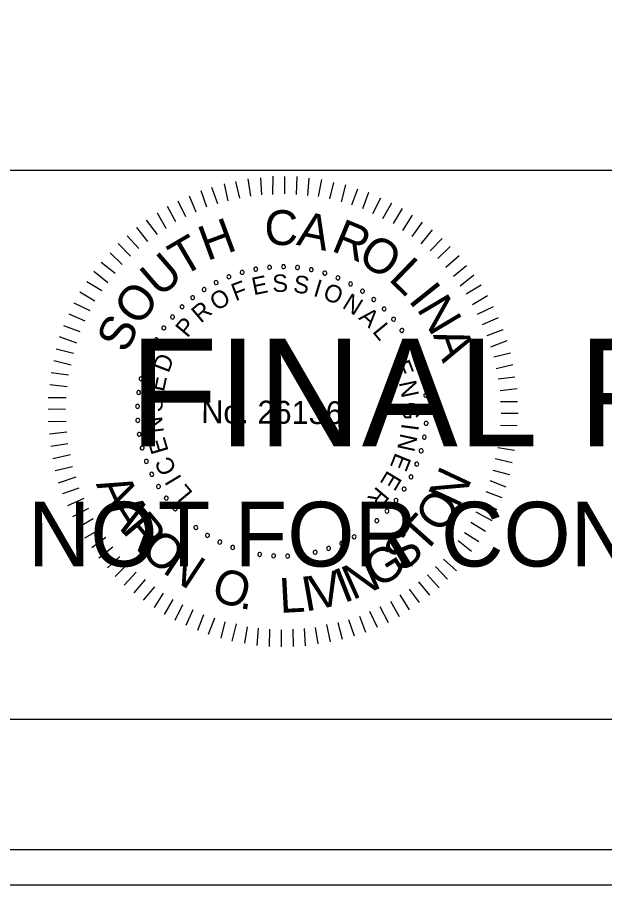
# Model space of a CAD drawing. Extents: x 967 to 1326, y 964 to 3704.
# Drawn here: x 1170.56 to 1189.3, y 1243.72 to 1271.36 of the extents above; entities that cross this region are included whole.
import ezdxf

# ---------------------------------------------------------------- set-up
doc = ezdxf.new("R2010")
doc.units = 0
for name, color, linetype in [('RD_SHT_Bndy', 7, 'Continuous'), ('RD_SHT_IplotShp', 7, 'Continuous'), ('RD_SHT_Misc1', 7, 'Continuous'), ('RD_SHT_Misc2', 7, 'Continuous'), ('RD_XS_TX_Station', 7, 'Continuous')]:
    doc.layers.add(name, color=color, linetype=linetype)

msp = doc.modelspace()

# ---------------------------------------------------------------- linework, layer by layer
at = {"layer": 'RD_SHT_Bndy'}
for p, q in [((996.114, 1266.486), (1323.886, 1266.486)), ((1323.886, 1248.983), (996.114, 1248.983))]:
    msp.add_line(p, q, dxfattribs=at)
at = {"layer": 'RD_SHT_IplotShp'}
for points in [[(967.409, 1243.72), (1326.285, 1243.72), (1326.285, 1463.72), (967.409, 1463.72)], [(988.525, 1244.84), (1326.285, 1244.84), (1326.285, 1462.6), (988.525, 1462.6)]]:
    msp.add_lwpolyline(points, close=True, dxfattribs=at)
at = {"layer": 'RD_SHT_Misc1'}
for p, q in [((1178.01, 1265.663), (1177.93, 1266.209)), ((1178.364, 1265.699), (1178.33, 1266.244)), ((1178.717, 1265.719), (1178.722, 1266.295)), ((1179.093, 1265.739), (1179.098, 1266.292)), ((1179.469, 1265.713), (1179.489, 1266.288)), ((1179.829, 1265.687), (1179.872, 1266.231)), ((1180.174, 1265.646), (1180.271, 1266.19)), ((1176.964, 1265.419), (1176.769, 1265.935)), ((1177.287, 1265.508), (1177.169, 1266.054)), ((1177.657, 1265.597), (1177.53, 1266.128)), ((1180.535, 1265.573), (1180.662, 1266.102)), ((1180.902, 1265.478), (1181.045, 1266.022)), ((1176.264, 1265.156), (1176.053, 1265.657)), ((1176.61, 1265.306), (1176.423, 1265.83)), ((1181.231, 1265.384), (1181.428, 1265.896)), ((1181.584, 1265.265), (1181.78, 1265.786)), ((1175.933, 1265.005), (1175.699, 1265.506)), ((1181.905, 1265.109), (1182.154, 1265.606)), ((1182.226, 1264.953), (1182.506, 1265.45)), ((1175.308, 1264.634), (1175.036, 1265.12)), ((1175.624, 1264.846), (1175.352, 1265.332)), ((1182.562, 1264.789), (1182.85, 1265.27)), ((1175.03, 1264.445), (1174.681, 1264.9)), ((1182.86, 1264.572), (1183.163, 1265.053)), ((1183.158, 1264.378), (1183.484, 1264.828)), ((1174.729, 1264.217), (1174.372, 1264.665)), ((1183.447, 1264.145), (1183.811, 1264.587)), ((1174.435, 1263.997), (1174.062, 1264.399)), ((1183.729, 1263.92), (1184.116, 1264.316)), ((1174.172, 1263.753), (1173.776, 1264.148)), ((1183.98, 1263.672), (1184.368, 1264.061)), ((1173.909, 1263.479), (1173.52, 1263.858)), ((1184.232, 1263.394), (1184.657, 1263.767)), ((1173.684, 1263.197), (1173.242, 1263.546)), ((1184.475, 1263.108), (1184.892, 1263.45)), ((1173.451, 1262.9), (1173.009, 1263.256)), ((1184.687, 1262.807), (1185.128, 1263.156)), ((1173.257, 1262.64), (1172.776, 1262.936)), ((1173.039, 1262.312), (1172.559, 1262.6)), ((1184.885, 1262.544), (1185.355, 1262.832)), ((1185.081, 1262.213), (1185.56, 1262.493)), ((1172.883, 1262.006), (1172.379, 1262.256)), ((1185.24, 1261.904), (1185.756, 1262.145)), ((1172.727, 1261.677), (1172.215, 1261.904)), ((1185.399, 1261.573), (1185.907, 1261.791)), ((1172.571, 1261.333), (1172.051, 1261.53)), ((1185.549, 1261.226), (1186.057, 1261.414)), ((1172.461, 1260.974), (1171.91, 1261.178)), ((1185.669, 1260.865), (1186.185, 1261.06)), ((1172.351, 1260.652), (1171.807, 1260.787)), ((1185.759, 1260.541), (1186.297, 1260.667)), ((1172.286, 1260.276), (1171.727, 1260.419)), ((1185.832, 1260.165), (1186.371, 1260.298)), ((1172.191, 1259.955), (1171.647, 1260.029)), ((1185.906, 1259.842), (1186.436, 1259.906)), ((1172.15, 1259.587), (1171.598, 1259.653)), ((1185.964, 1259.473), (1186.51, 1259.53)), ((1172.124, 1259.234), (1171.548, 1259.239)), ((1185.977, 1259.12), (1186.514, 1259.115)), ((1172.105, 1258.866), (1171.545, 1258.871)), ((1185.997, 1258.751), (1186.542, 1258.747)), ((1172.118, 1258.482), (1171.542, 1258.471)), ((1185.971, 1258.368), (1186.508, 1258.348)), ((1172.138, 1258.136), (1171.585, 1258.072)), ((1185.952, 1258.022), (1186.497, 1257.949)), ((1172.173, 1257.768), (1171.627, 1257.688)), ((1185.888, 1257.655), (1186.417, 1257.566)), ((1172.262, 1257.414), (1171.701, 1257.296)), ((1185.808, 1257.302), (1186.345, 1257.175)), ((1172.321, 1257.037), (1171.774, 1256.911)), ((1185.729, 1256.926), (1186.265, 1256.792)), ((1172.425, 1256.707), (1171.871, 1256.519)), ((1185.634, 1256.597), (1186.146, 1256.401)), ((1172.53, 1256.36), (1172.007, 1256.173)), ((1185.508, 1256.253), (1186.013, 1256.057)), ((1172.681, 1256.029), (1172.165, 1255.788)), ((1172.831, 1255.705), (1172.323, 1255.441)), ((1185.352, 1255.924), (1185.857, 1255.675)), ((1185.188, 1255.603), (1185.7, 1255.33)), ((1172.982, 1255.374), (1172.497, 1255.094)), ((1185.024, 1255.274), (1185.498, 1254.987)), ((1173.194, 1255.042), (1172.709, 1254.762)), ((1184.822, 1254.946), (1185.288, 1254.658)), ((1173.384, 1254.78), (1172.936, 1254.453)), ((1184.62, 1254.687), (1185.055, 1254.353)), ((1173.612, 1254.478), (1173.164, 1254.129)), ((1184.403, 1254.389), (1184.814, 1254.033)), ((1173.832, 1254.177), (1173.437, 1253.812)), ((1184.155, 1254.092), (1184.574, 1253.72)), ((1174.091, 1253.945), (1173.689, 1253.541)), ((1183.899, 1253.864), (1184.28, 1253.454)), ((1174.35, 1253.674), (1173.97, 1253.263)), ((1183.644, 1253.597), (1184.024, 1253.18)), ((1174.64, 1253.442), (1174.275, 1253.022)), ((1174.937, 1253.209), (1174.58, 1252.782)), ((1183.358, 1253.37), (1183.715, 1252.944)), ((1175.212, 1253.014), (1174.932, 1252.549)), ((1182.764, 1252.952), (1183.059, 1252.482)), ((1183.065, 1253.141), (1183.384, 1252.709)), ((1175.525, 1252.812), (1175.245, 1252.331)), ((1182.463, 1252.755), (1182.743, 1252.269)), ((1175.83, 1252.633), (1175.588, 1252.136)), ((1176.159, 1252.477), (1175.94, 1251.98)), ((1181.8, 1252.431), (1182.041, 1251.93)), ((1182.124, 1252.581), (1182.396, 1252.08)), ((1176.503, 1252.321), (1176.307, 1251.816)), ((1176.855, 1252.211), (1176.651, 1251.69)), ((1177.177, 1252.1), (1177.05, 1251.572)), ((1181.122, 1252.175), (1181.31, 1251.652)), ((1181.476, 1252.28), (1181.664, 1251.771)), ((1177.545, 1252.036), (1177.409, 1251.484)), ((1177.897, 1251.933), (1177.808, 1251.412)), ((1178.25, 1251.892), (1178.207, 1251.34)), ((1178.603, 1251.866), (1178.598, 1251.313)), ((1178.978, 1251.84), (1178.974, 1251.295)), ((1179.355, 1251.86), (1179.365, 1251.307)), ((1179.715, 1251.88), (1179.749, 1251.327)), ((1180.061, 1251.915), (1180.149, 1251.393)), ((1180.423, 1252.012), (1180.541, 1251.458)), ((1180.791, 1252.07), (1180.926, 1251.54))]:
    msp.add_line(p, q, dxfattribs=at)
for centre, start, end in [((1178.609, 1263.397), 5.0653, 185.0653), ((1179.055, 1263.414), 359.5268, 179.5268), ((1179.055, 1263.414), 179.5268, 359.5268), ((1179.5, 1263.388), 353.9884, 173.9884), ((1177.312, 1263.091), 21.6807, 201.6807), ((1177.734, 1263.235), 16.1422, 196.1422), ((1177.734, 1263.235), 196.1422, 16.1422), ((1178.168, 1263.337), 10.6038, 190.6038), ((1178.168, 1263.337), 190.6038, 10.6038), ((1178.609, 1263.397), 185.0653, 5.0653), ((1179.5, 1263.388), 173.9884, 353.9884), ((1179.94, 1263.319), 168.4499, 348.4499), ((1179.94, 1263.319), 348.4499, 168.4499), ((1180.372, 1263.208), 162.9114, 342.9114), ((1180.372, 1263.208), 342.9114, 162.9114), ((1176.906, 1262.908), 27.2191, 207.2191), ((1176.906, 1262.908), 207.2191, 27.2191), ((1177.312, 1263.091), 201.6807, 21.6807), ((1180.79, 1263.056), 157.373, 337.373), ((1180.79, 1263.056), 337.373, 157.373), ((1181.193, 1262.864), 151.8345, 331.8345), ((1181.193, 1262.864), 331.8345, 151.8345), ((1176.52, 1262.686), 32.7576, 212.7576), ((1176.52, 1262.686), 212.7576, 32.7576), ((1181.574, 1262.634), 146.2961, 326.2961), ((1181.574, 1262.634), 326.2961, 146.2961), ((1176.156, 1262.428), 38.2961, 218.2961), ((1176.156, 1262.428), 218.2961, 38.2961), ((1181.932, 1262.368), 140.7576, 320.7576), ((1181.932, 1262.368), 320.7576, 140.7576), ((1175.82, 1262.135), 43.8345, 223.8345), ((1175.82, 1262.135), 223.8345, 43.8345), ((1182.263, 1262.069), 135.2191, 315.2191), ((1182.263, 1262.069), 315.2191, 135.2191), ((1175.513, 1261.812), 49.373, 229.373), ((1175.513, 1261.812), 229.373, 49.373), ((1182.563, 1261.74), 129.6807, 309.6807), ((1182.563, 1261.74), 309.6807, 129.6807), ((1175.239, 1261.461), 54.9114, 234.9114), ((1175.239, 1261.461), 234.9114, 54.9114), ((1182.83, 1261.383), 124.1422, 304.1422), ((1182.83, 1261.383), 304.1422, 124.1422), ((1175, 1261.085), 60.4499, 240.4499), ((1175, 1261.085), 240.4499, 60.4499), ((1183.061, 1261.002), 118.6038, 298.6038), ((1183.061, 1261.002), 298.6038, 118.6038), ((1174.798, 1260.687), 65.9884, 245.9884), ((1174.798, 1260.687), 245.9884, 65.9884), ((1183.255, 1260.601), 113.0653, 293.0653), ((1183.255, 1260.601), 293.0653, 113.0653), ((1174.636, 1260.272), 71.5268, 251.5268), ((1174.636, 1260.272), 251.5268, 71.5268), ((1183.408, 1260.182), 107.5268, 287.5268), ((1183.408, 1260.182), 287.5268, 107.5268), ((1174.514, 1259.843), 77.0653, 257.0653), ((1174.514, 1259.843), 257.0653, 77.0653), ((1183.521, 1259.751), 101.9884, 281.9884), ((1183.521, 1259.751), 281.9884, 101.9884), ((1174.435, 1259.405), 82.6038, 262.6038), ((1174.435, 1259.405), 262.6038, 82.6038), ((1183.592, 1259.311), 96.4499, 276.4499), ((1183.592, 1259.311), 276.4499, 96.4499), ((1174.398, 1258.961), 88.1422, 268.1422), ((1174.398, 1258.961), 268.1422, 88.1422), ((1183.619, 1258.866), 90.9114, 270.9114), ((1183.619, 1258.866), 270.9114, 90.9114), ((1174.404, 1258.515), 93.6807, 273.6807), ((1174.404, 1258.515), 273.6807, 93.6807), ((1183.604, 1258.421), 85.373, 265.373), ((1183.604, 1258.421), 265.373, 85.373), ((1174.453, 1258.072), 99.2191, 279.2191), ((1174.453, 1258.072), 279.2191, 99.2191), ((1183.546, 1257.979), 79.8345, 259.8345), ((1183.546, 1257.979), 259.8345, 79.8345), ((1174.545, 1257.636), 104.7576, 284.7576), ((1174.545, 1257.636), 284.7576, 104.7576), ((1183.445, 1257.545), 74.2961, 254.2961), ((1183.445, 1257.545), 254.2961, 74.2961), ((1174.678, 1257.211), 110.2961, 290.2961), ((1174.678, 1257.211), 290.2961, 110.2961), ((1183.303, 1257.122), 68.7576, 248.7576), ((1183.303, 1257.122), 248.7576, 68.7576), ((1174.852, 1256.8), 115.8345, 295.8345), ((1174.852, 1256.8), 295.8345, 115.8345), ((1183.121, 1256.716), 63.2191, 243.2191), ((1183.121, 1256.716), 243.2191, 63.2191), ((1175.065, 1256.409), 121.373, 301.373), ((1175.065, 1256.409), 301.373, 121.373), ((1182.9, 1256.328), 57.6807, 237.6807), ((1182.9, 1256.328), 237.6807, 57.6807), ((1175.314, 1256.039), 126.9114, 306.9114), ((1175.314, 1256.039), 306.9114, 126.9114), ((1182.643, 1255.964), 52.1422, 232.1422), ((1182.643, 1255.964), 232.1422, 52.1422), ((1175.598, 1255.696), 132.4499, 312.4499), ((1175.598, 1255.696), 312.4499, 132.4499), ((1182.353, 1255.627), 46.6038, 226.6038), ((1175.914, 1255.381), 137.9884, 317.9884), ((1175.914, 1255.381), 317.9884, 137.9884), ((1182.353, 1255.627), 226.6038, 46.6038), ((1176.258, 1255.099), 143.5268, 323.5268), ((1176.258, 1255.099), 323.5268, 143.5268), ((1182.03, 1255.319), 41.0653, 221.0653), ((1182.03, 1255.319), 221.0653, 41.0653), ((1176.629, 1254.851), 149.0653, 329.0653), ((1176.629, 1254.851), 329.0653, 149.0653), ((1181.305, 1254.803), 29.9884, 209.9884), ((1181.68, 1255.043), 35.5268, 215.5268), ((1181.68, 1255.043), 215.5268, 35.5268), ((1177.021, 1254.639), 154.6038, 334.6038), ((1177.021, 1254.639), 334.6038, 154.6038), ((1180.908, 1254.6), 24.4499, 204.4499), ((1180.908, 1254.6), 204.4499, 24.4499), ((1181.305, 1254.803), 209.9884, 29.9884), ((1177.432, 1254.467), 160.1422, 340.1422), ((1177.432, 1254.467), 340.1422, 160.1422), ((1177.858, 1254.335), 165.6807, 345.6807), ((1177.858, 1254.335), 345.6807, 165.6807), ((1178.294, 1254.245), 351.2191, 171.2191), ((1179.627, 1254.232), 7.8345, 187.8345), ((1180.065, 1254.313), 13.373, 193.373), ((1180.065, 1254.313), 193.373, 13.373), ((1180.494, 1254.436), 18.9114, 198.9114), ((1180.494, 1254.436), 198.9114, 18.9114), ((1178.294, 1254.245), 171.2191, 351.2191), ((1178.737, 1254.198), 356.7576, 176.7576), ((1178.737, 1254.198), 176.7576, 356.7576), ((1179.183, 1254.193), 2.2961, 182.2961), ((1179.183, 1254.193), 182.2961, 2.2961), ((1179.627, 1254.232), 187.8345, 7.8345)]:
    msp.add_arc(centre, 0.0627, start, end, dxfattribs=at)
at = {"layer": 'RD_XS_TX_Station'}
msp.add_lwpolyline([(967.409, 1243.72), (1326.285, 1243.72), (1326.285, 1463.72), (967.409, 1463.72)], close=True, dxfattribs=at)

# ---------------------------------------------------------------- texts
at = {"layer": 'RD_SHT_Misc1'}
for s, height, rotation, p in [('C', 1.11, 359.5482, (1178.442, 1264.108)), ('A', 1.11, 348.1981, (1179.439, 1264.115)), ('H', 1.11, 20.3637, (1176.614, 1263.587)), ('R', 1.11, 337.4344, (1180.541, 1263.937)), ('T', 1.11, 30.4992, (1175.828, 1263.072)), ('O', 1.108, 326.5869, (1181.366, 1263.609)), ('U', 1.11, 40.8022, (1175.102, 1262.403)), ('L', 1.11, 315.9488, (1182.373, 1263.003)), ('E', 0.557, 11.4103, (1178.103, 1262.503)), ('S', 0.557, 2.208, (1178.709, 1262.601)), ('S', 0.557, 352.6608, (1179.346, 1262.599)), ('F', 0.557, 20.6127, (1177.52, 1262.309)), ('I', 0.557, 343.1136, (1179.975, 1262.491)), ('O', 0.557, 338.4392, (1180.274, 1262.401)), ('I', 1.11, 308.6613, (1183.011, 1262.338)), ('O', 1.11, 52.0267, (1174.435, 1261.474)), ('O', 0.557, 30.8477, (1176.917, 1261.987)), ('N', 0.557, 328.2042, (1180.896, 1262.12)), ('N', 1.11, 300.7037, (1183.285, 1262.075)), ('R', 0.557, 40.3949, (1176.415, 1261.594)), ('A', 0.557, 318.657, (1181.424, 1261.762)), ('S', 1.108, 63.2511, (1174.029, 1260.619)), ('P', 0.557, 49.9421, (1175.985, 1261.124)), ('L', 0.557, 309.4546, (1181.869, 1261.339)), ('A', 1.11, 289.4792, (1183.814, 1261.243)), ('D', 0.557, 69.0364, (1175.386, 1260.003)), ('E', 0.557, 291.049, (1182.53, 1260.307)), ('E', 0.557, 78.2388, (1175.238, 1259.407)), ('N', 0.557, 281.8466, (1182.728, 1259.726)), ('S', 0.557, 87.786, (1175.187, 1258.772)), ('No. 26136', 0.7311, 359.5268, (1176.429, 1258.43)), ('G', 0.557, 272.2995, (1182.833, 1259.097)), ('N', 0.557, 97.3332, (1175.242, 1258.137)), ('I', 0.557, 262.4084, (1182.83, 1258.437)), ('E', 0.557, 106.5355, (1175.394, 1257.541)), ('N', 0.557, 257.7339, (1182.789, 1258.127)), ('C', 0.557, 116.4266, (1175.661, 1256.938)), ('E', 0.557, 248.1867, (1182.628, 1257.511)), ('I', 0.557, 121.1011, (1175.823, 1256.67)), ('E', 0.557, 238.9844, (1182.378, 1256.949)), ('N', 1.105, 64.8922, (1184.632, 1255.684)), ('A', 1.105, 294.7297, (1173.062, 1256.486)), ('L', 0.557, 129.9595, (1176.187, 1256.204)), ('R', 0.557, 229.782, (1182.041, 1256.435)), ('A', 1.105, 302.2892, (1173.414, 1255.72)), ('O', 1.105, 56.2059, (1184.102, 1254.874)), ('R', 1.105, 309.8487, (1173.865, 1255.007)), ('T', 1.105, 48.2685, (1183.515, 1254.211)), ('O', 1.105, 317.7861, (1174.434, 1254.33)), ('S', 1.105, 40.3311, (1182.842, 1253.636)), ('N', 1.105, 326.4725, (1175.158, 1253.686)), ('G', 1.105, 32.0198, (1182.059, 1253.14)), ('N', 1.105, 24.0824, (1181.252, 1252.776)), ('O', 1.105, 342.3472, (1176.697, 1252.82)), ('V', 1.105, 12.7741, (1180.033, 1252.457)), ('I', 1.105, 21.4605, (1180.976, 1252.681)), ('L', 1.105, 2.9677, (1178.943, 1252.379)), ('I', 1.105, 10.1523, (1179.743, 1252.418)), ('.', 1.105, 351.0336, (1177.623, 1252.536))]:
    msp.add_text(s, height=height, rotation=rotation, dxfattribs=at).set_placement(p)
at = {"layer": 'RD_SHT_Misc2'}
for s, height, p in [('FINAL PLANS', 3.4375, (1174.145, 1257.685)), ('NOT FOR CONSTRUCTION', 2.0625, (1170.901, 1253.86))]:
    msp.add_text(s, height=height, dxfattribs=at).set_placement(p)

doc.saveas('drawing.dxf')
